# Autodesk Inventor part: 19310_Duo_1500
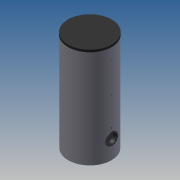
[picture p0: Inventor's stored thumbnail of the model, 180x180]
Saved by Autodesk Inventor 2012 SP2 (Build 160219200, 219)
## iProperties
allow_slope_adjustment: 0 ul
connection_type: 13 ul
flow_configuration2: 1 ul
flow_direction: 2 ul
loss_method: 0 ul
radius: 28,500 mm
radius: 12,250 mm
description: 0:0:19311_Duo_1500
manufacturer: 0:0:Flamco Group
model: 0:0:Duo 1500
url: 0:0:www.flamcogroup.com
radius: 15,375 mm
Created: 2014-05
Part Number: 19310_Duo_1500
Material: Default
Document SubType Name: Modeling
Designer: michel
Density: 1 g/cm^3
radius: 9,500 mm
Author: michel
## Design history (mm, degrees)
sketch "Sketch1"
  geometry: C1 r 500 at (0, 0); 1 further point
  constraints: 1 centre point, 1 coincident
  dimensions: "d0" = 1000 diameter of C1
extrude "Extrusion1" new body sketch "Sketch1" distance "d1" = 2320; taper "d2" = 0 deg
sketch "Sketch2"
  geometry: L1 (-500, 2320)-(500, 2320) reference; L2 (-500, 0)-(500, 0) reference; L3 (500, 0)-(500, 2320) reference; L4 (500, 2320)-(505, 2320); L5 (505, 2320)-(505, 2270); L6 (505, 2270)-(500, 2270); L7 (500, 2270)-(500, 2320); L8 (0, -446)-(0, 2676) reference; 1 further point
  constraints: 8 end point, 2 parallel, 1 horizontal, 1 perpendicular
  dimensions: "d3" = 5 distance of L5.end L6.end; "d4" = 50 distance of L4.end L5.end
revolve "Revolution1" sketch "Sketch2" stored, may be unused: angle "d5" = 90 deg
workplane "Work Plane1"
workplane "Work Plane2"
workplane "Work Plane3"
workplane "Work Plane4"
workplane "Work Plane5"
workplane "Work Plane6"
workplane "Work Plane11"
workplane "Work Plane12"
workplane "Work Plane13"
sketch "Sketch3"
  geometry: L1 (701.4, 2235)-(-701.4, 2235) reference; L2 (701.4, 1735)-(-701.4, 1735) reference; L3 (701.4, 1555)-(-701.4, 1555) reference; L4 (701.4, 435)-(-701.4, 435) reference; L5 (701.4, 85)-(-701.4, 85) reference; L6 (500, 0)-(500, 2270) reference; L7 (500, 2235)-(460, 2235); L8 (460, 2235)-(460, 2264.805); L9 (460, 2264.805)-(500, 2264.805); L10 (500, 1735)-(460, 1735); L11 (460, 1735)-(460, 1751.625); L12 (460, 1751.625)-(500, 1751.625); L13 (500, 1751.625)-(500, 1735); L14 (335, 2206.5)-(335, 2205.195); L15 (335, 2205.195)-(501, 2205.195); L16 (501, 2205.195)-(501, 2206.5); L17 (501, 2206.5)-(335, 2206.5); L18 (460, 1555)-(460, 1584.805); L19 (500, 1555)-(460, 1555); L20 (460, 1584.805)-(500, 1584.805); L21 (500, 1584.805)-(500, 1555); L22 (335, 1526.5)-(335, 1525.195); L23 (335, 1525.195)-(501, 1525.195); L24 (501, 1525.195)-(501, 1526.5); L25 (501, 1526.5)-(335, 1526.5); L26 (460, 464.805)-(500, 464.805); L27 (460, 435)-(460, 464.805); L28 (500, 435)-(460, 435); L29 (500, 464.805)-(500, 435); L30 (501, 406.5)-(335.165, 406.5); L31 (335.165, 406.5)-(335.165, 405.195); L32 (335.165, 405.195)-(501, 405.195); L33 (501, 405.195)-(501, 406.5); L34 (460, 114.805)-(500, 114.805); L35 (460, 85)-(460, 114.805); L36 (500, 85)-(460, 85); L37 (500, 114.805)-(500, 85); L38 (501, 56.5)-(335, 56.5); L39 (335, 56.5)-(335, 55.195); L40 (335, 55.195)-(501, 55.195); L41 (501, 55.195)-(501, 56.5); L42 (335, 1719.625)-(335, 1718.375); L43 (501, 1718.375)-(501, 1719.625); L44 (501, 1719.625)-(335, 1719.625); L45 (-707, 2020)-(707, 2020) reference; L46 (701.4, 1300)-(-701.4, 1300) reference; L47 (-500, 0)-(-500, 2270) reference; L48 (-500, 2020)-(-460, 2020); L49 (-460, 2020)-(-460, 2030.475); L50 (-460, 2030.475)-(-500, 2030.475); L51 (-500, 2030.475)-(-500, 2020); L52 (-501, 2009.525)-(-335, 2009.525); L53 (-335, 2009.525)-(-335, 2010.5); L54 (-335, 2010.5)-(-501, 2010.5); L55 (-501, 2010.5)-(-501, 2009.525); L56 (-500, 1300)-(-335, 1300); L57 (-335, 1300)-(-335, 1313.22); L58 (-335, 1313.22)-(-500, 1313.22); L59 (-500, 1313.22)-(-500, 1300); L60 (-501, 1286.78)-(-335, 1286.78); L61 (-335, 1286.78)-(-335, 1287.75); L62 (-335, 1287.75)-(-501, 1287.75); L63 (-501, 1287.75)-(-501, 1286.78); L64 (500, 2264.805)-(500, 2235)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; 2 further points
  constraints: 128 end point, 20 parallel, 9 horizontal, 9 perpendicular, 8 point on line, 1 collinear
  dimensions: "d19" = 40 distance of L8.end L9.end; "d21" = 40 distance of L11.end L12.end; "d70" = 29.805 distance between parallel lines of L1 L9; "d73" = 40 distance of L18.end L20.end; "d74" = 40 distance of L26.start L26.end; "d75" = 40 distance of L34.start L34.end; "d76" = 29.805 distance between parallel lines of L3 L20; "d85" = 16.625 distance between parallel lines of L2 L12; "d108" = 29.805 distance between parallel lines of L1 L15 (derived); "d109" = 1.305 distance between parallel lines of L17 L15 (derived); "d110" = 16.625 distance between parallel lines of L10 L12 (= d85); "d113" = 29.805 distance between parallel lines of L19 L20 (= d76); "d114" = 29.805 distance between parallel lines of L23 L3 (derived); "d115" = 1.305 distance between parallel lines of L25 L23 (derived); "d116" = 29.805 distance between parallel lines of L4 L26; "d117" = 29.805 distance of L26.start L27.start (= d116); "d118" = 29.805 distance between parallel lines of L32 L4 (derived); "d119" = 1.305 distance between parallel lines of L30 L32 (derived); "d120" = 29.805 distance from line of L34 L35.start (= d121); "d121" = 29.805 distance between parallel lines of L5 L34; "d122" = 29.805 distance between parallel lines of L40 L5 (derived); "d123" = 1.305 distance between parallel lines of L38 L40 (derived); "d129" = 40 distance of L50.end L49.end; "d130" = 10.475 distance of L49.end L48.end; "d131" = 10.475 distance between parallel lines of L45 L52; "d132" = 0.975 distance between parallel lines of L54 L52; "d134" = 13.22 distance between parallel lines of L46 L58; "d135" = 13.22 distance between parallel lines of L46 L60 (derived); "d136" = 0.97 distance between parallel lines of L62 L60 (derived); "d154" = 1 distance between parallel lines of L47 L55; "d155" = 1 distance between parallel lines of L47 L63; "d157" = 1 distance between parallel lines of L6 L16; "d158" = 0 distance between parallel lines of L6 L13; "d159" = 1 distance between parallel lines of L6 L43; "d160" = 0 distance between parallel lines of L6 L21; "d161" = 1 distance between parallel lines of L6 L24; "d162" = 0 distance between parallel lines of L6 L29; "d163" = 1 distance between parallel lines of L6 L33; "d164" = 0 distance between parallel lines of L6 L37; "d165" = 1 distance between parallel lines of L6 L41; "d166" = 16.625 distance between parallel lines of L65 L2 (derived); "d167" = 1.25 distance between parallel lines of L44 L65 (derived); "d173" = 0 distance between parallel lines of L6 L64; "d181" = 40 distance of L69.end L68.end; "d182" = 13.22 distance of L68.end L67.end; "d183" = 13.22 distance between parallel lines of L66 L73 (derived); "d184" = 0.97 distance between parallel lines of L71 L73 (derived); "d185" = 1 distance between parallel lines of L47 L74
revolve "Revolution2" stored, may be unused: angle "d23" = 90 deg
sketch "Sketch5"
  geometry: L1 (-500, 0)-(-500, 2270) reference; L2 (-500, 0)-(-500, 435); L3 (-220, 435)-(-594, 435); L4 (-500, 435)-(-512.5, 435); L5 (-512.5, 435)-(-512.5, 575); L6 (-512.5, 575)-(-500, 575); L7 (-500, 575)-(-500, 435); L8 (-500, 0)-(500, 0) reference; 1 further point
  constraints: 12 end point, 2 parallel, 2 perpendicular, 1 horizontal, 1 point on line
  dimensions: "d35" = 435 distance of L1.start L2.end; "d36" = 12.5 distance of L5.end L6.end; "d37" = 140 distance of L4.end L5.end; "d124" = 435 distance between parallel lines of L8 L3 (= d35)
revolve "Revolution7" sketch "Sketch5" stored, may be unused: angle "d38" = 90 deg
sketch "Sketch6"
  geometry: C1 r 122.5 at (0, 0); A1 r 140 centre (0, 0) between (140, 0) and (-140, 0) reference; 1 further point
  constraints: 1 centre point, 1 coincident
  dimensions: "d39" = 245 diameter of C1
extrude "Extrusion3" join sketch "Sketch6" stored distance "d40" = 40; taper "d41" = 0 deg
sketch "Sketch7"
  geometry: C1 r 140 at (0, 0) reference; C2 r 102.5 at (0, 0); 1 further point
  constraints: 1 centre point, 1 coincident
  dimensions: "d42" = 205 diameter of C2
extrude "Extrusion4" cut sketch "Sketch7" distance "d43" = 80; taper "d44" = 0 deg
revolve "Revolution9" stored, may be unused: angle "d69" = 90 deg
revolve "Revolution10" stored, may be unused: angle "d92" = 90 deg
revolve "Revolution11" stored, may be unused: angle "d93" = 90 deg
revolve "Revolution12" stored, may be unused: angle "d94" = 90 deg
revolve "Revolution13" stored, may be unused: angle "d95" = 90 deg
revolve "Revolution14" stored, may be unused: angle "d96" = 90 deg
revolve "Revolution15" stored, may be unused: angle "d97" = 90 deg
revolve "Revolution16" stored, may be unused: angle "d98" = 90 deg
revolve "Revolution17" stored, may be unused: angle "d99" = 90 deg
revolve "Revolution18" stored, may be unused: angle "d138" = 90 deg
revolve "Revolution19" stored, may be unused: angle "d139" = 90 deg
revolve "Revolution20" stored, may be unused: angle "d140" = 90 deg
revolve "Revolution21" stored, may be unused: angle "d141" = 90 deg
revolve "Revolution22" stored, may be unused: angle "d186" = 90 deg
revolve "Revolution23" stored, may be unused: angle "d187" = 90 deg
body "Solid1"
node "Projected Loop1"
other parameters: "d12" = 0, "d174" = -2235, "d175" = -1735, "d176" = -1555, "d177" = -435, "d178" = -85
